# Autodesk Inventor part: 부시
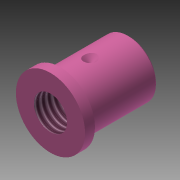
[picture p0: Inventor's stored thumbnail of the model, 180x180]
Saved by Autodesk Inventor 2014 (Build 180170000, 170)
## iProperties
Created: 2019-04
Part Number: 부시
Material: 강철, 연강
Document SubType Name: Modeling
Designer: mduedu
Density: 1 g/cm^3
Appearance: Pink
Author: mduedu
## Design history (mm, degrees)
sketch "스케치1"
  geometry: L1 (0, 0)-(3, 0); L2 (3, 0)-(3, 10.5); L3 (3, 10.5)-(0, 10.5); L4 (0, 10.5)-(0, 0); L5 (3, 0)-(24, 0); L6 (24, 0)-(24, 8.5); L7 (24, 8.5)-(3, 8.5); L8 (3, 8.5)-(3, 0)
  constraints: 16 end point, 4 parallel, 2 horizontal, 2 perpendicular
  dimensions: "d0" = 3 distance of L2.end L3.end; "d2" = 24 distance between parallel lines of L6 L4; "d3" = 17 diameter of L7 L5; "d4" = 21 diameter of L3 L1
revolve "회전1" sketch "스케치1" stored, may be unused: angle "d5" = 90 deg
sketch "스케치2"
  geometry: L1 (3, 8.5)-(24, 8.5) reference; L2 (12, 8.5)-(12, 6.5); L3 (12, 6.5)-(14, 8.5); L4 (0, -10.5)-(0, 10.5) reference; 1 further point
  constraints: 4 end point, 2 point on line, 1 perpendicular
  dimensions: "d6" = 12 distance from line of L2.start L4; "d7" = 2 distance of L2.start L3.end; "d8" = 45 deg angle of L3 L2
revolve "회전2" sketch "스케치2" stored, may be unused: angle "d9" = 90 deg
hole "구멍1" diameter "d12" = 10.106; stored, may be unused: countersink angle "d16" = 90 deg, drill point angle "d18" = 118 deg; dims "d10" = 10, "d11" = 10, "d13" = 39, "d14" = 4, "d15" = 2, "d17" = 8
chamfer "모따기1" distance "d19" = 0.5; stored, may be unused: second distance "d20" = 2, angle "d21" = 45 deg
node "작업점1"
  node "작업 평면1"
  node "작업축1"
workaxis "Work Axis2"
sketch "Sketch3"
  geometry: L1 (3, 8.5)-(23.5, 8.5) reference; L2 (12, 6.5)-(14, 8.5) reference; L3 (12, 6.5)-(14, 8.5); 1 further point
  constraints: 2 end point, 1 collinear
workpoint "Work Point2"
node "솔리드1"
